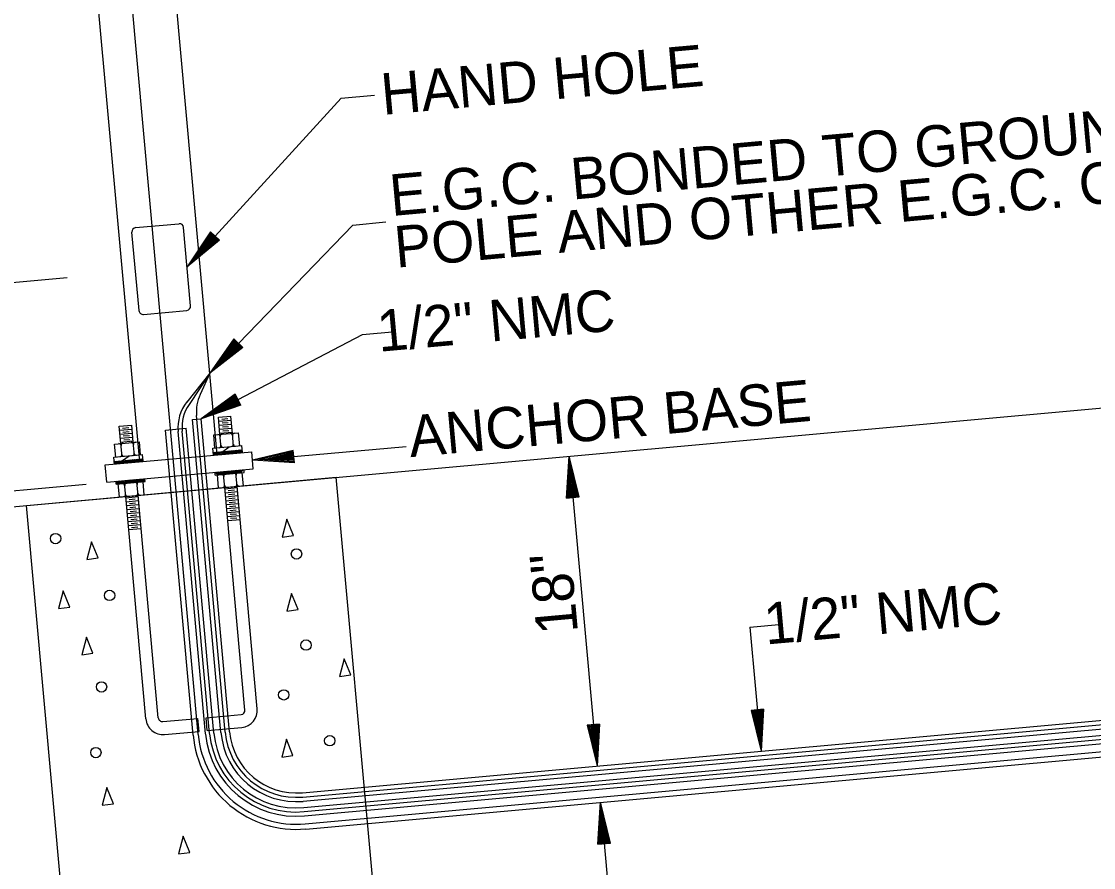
# Model space of a CAD drawing. Extents: x 1277218 to 1279252, y 196860 to 197529.
# Drawn here: x 1278336.3 to 1278454.9, y 197271.8 to 197365.4 of the extents above; entities that cross this region are included whole.
import ezdxf

# ---------------------------------------------------------------- set-up
doc = ezdxf.new("R2010")
doc.units = 0
doc.layers.add('R_Point Sym', color=7, linetype='Continuous')

msp = doc.modelspace()

# ---------------------------------------------------------------- linework, layer by layer
at = {"layer": 'R_Point Sym'}
for p, q in [((1278349.34, 197316.66), (1278341, 197408.77)), ((1278357.91, 197317.43), (1278349.57, 197409.55)), ((1278355.82, 197286.47), (1278346.71, 197386.98)), ((1278354.59, 197338.26), (1278371.65, 197356.9)), ((1278371.65, 197356.9), (1278375.32, 197357.23)), ((1278348.89, 197342.58), (1278353.69, 197343.01)), ((1278354.98, 197333.91), (1278354.19, 197342.6)), ((1278357.1, 197326.46), (1278372.92, 197342.87)), ((1278372.92, 197342.87), (1278376.59, 197343.21)), ((1278349.27, 197333.4), (1278348.48, 197342.08)), ((1278357.17, 197342.11), (1278354.59, 197338.26)), ((1278358.19, 197341.18), (1278354.59, 197338.26)), ((1278357.26, 197342.03), (1278355.1, 197338.82)), ((1278358.11, 197341.26), (1278355.1, 197338.82)), ((1278357.35, 197341.95), (1278355.64, 197339.41)), ((1278358.02, 197341.34), (1278355.64, 197339.41)), ((1278357.43, 197341.88), (1278356.15, 197339.97)), ((1278357.93, 197341.41), (1278356.15, 197339.97)), ((1278357.52, 197341.8), (1278356.68, 197340.54)), ((1278357.85, 197341.49), (1278356.68, 197340.54)), ((1278358.19, 197341.18), (1278357.17, 197342.11)), ((1278357.6, 197341.72), (1278357.19, 197341.11)), ((1278357.76, 197341.57), (1278357.19, 197341.11)), ((1278328.02, 197335.85), (1278341.33, 197337.06)), ((1278349.76, 197332.98), (1278354.56, 197333.42)), ((1278356.15, 197321.42), (1278374.02, 197330.76)), ((1278374.02, 197330.76), (1278377.68, 197331.09)), ((1278359.76, 197330.26), (1278357.1, 197326.46)), ((1278360.76, 197329.31), (1278357.1, 197326.46)), ((1278359.85, 197330.18), (1278357.62, 197327.02)), ((1278360.68, 197329.39), (1278357.62, 197327.02)), ((1278359.93, 197330.1), (1278358.17, 197327.59)), ((1278360.59, 197329.47), (1278358.17, 197327.59)), ((1278360.01, 197330.02), (1278358.7, 197328.14)), ((1278360.51, 197329.55), (1278358.7, 197328.14)), ((1278360.1, 197329.94), (1278359.23, 197328.7)), ((1278360.42, 197329.63), (1278359.23, 197328.7)), ((1278360.76, 197329.31), (1278359.76, 197330.26)), ((1278360.18, 197329.86), (1278359.76, 197329.26)), ((1278360.34, 197329.71), (1278359.76, 197329.26)), ((1278276.09, 197306.34), (1278517.66, 197328.23)), ((1278357.1, 197326.46), (1278354.57, 197323.28)), ((1278357.1, 197326.46), (1278354.8, 197323.02)), ((1278357.1, 197326.46), (1278356.03, 197324.11)), ((1278359.9, 197324.16), (1278356.15, 197321.42)), ((1278359.95, 197324.06), (1278356.83, 197321.78)), ((1278360.01, 197323.95), (1278357.53, 197322.14)), ((1278360.43, 197323.14), (1278357.53, 197322.14)), ((1278360.06, 197323.85), (1278358.21, 197322.5)), ((1278360.38, 197323.24), (1278358.21, 197322.5)), ((1278360.11, 197323.75), (1278358.9, 197322.86)), ((1278360.32, 197323.35), (1278358.9, 197322.86)), ((1278360.17, 197323.64), (1278359.58, 197323.21)), ((1278360.27, 197323.45), (1278359.58, 197323.21)), ((1278360.54, 197322.94), (1278359.9, 197324.16)), ((1278360.54, 197322.94), (1278356.15, 197321.42)), ((1278360.48, 197323.04), (1278356.83, 197321.78)), ((1278355.2, 197321.33), (1278356.15, 197321.42)), ((1278358.34, 197286.69), (1278355.2, 197321.33)), ((1278358.81, 197286.74), (1278355.64, 197321.8)), ((1278359.29, 197286.78), (1278356.15, 197321.42)), ((1278358.06, 197321.59), (1278359.43, 197321.72)), ((1278358.23, 197319.69), (1278358.06, 197321.59)), ((1278358.1, 197321.15), (1278359.47, 197321.28)), ((1278358.13, 197320.71), (1278359.51, 197320.84)), ((1278358.42, 197321.4), (1278359.1, 197321.46)), ((1278358.46, 197320.96), (1278359.14, 197321.02)), ((1278359.6, 197319.81), (1278359.43, 197321.72)), ((1278347.08, 197320.6), (1278348.46, 197320.72)), ((1278347.26, 197318.69), (1278347.08, 197320.6)), ((1278347.12, 197320.16), (1278348.5, 197320.28)), ((1278347.16, 197319.72), (1278348.54, 197319.84)), ((1278347.45, 197320.4), (1278348.13, 197320.46)), ((1278347.49, 197319.96), (1278348.17, 197320.02)), ((1278347.53, 197319.52), (1278348.21, 197319.58)), ((1278348.63, 197318.82), (1278348.46, 197320.72)), ((1278352.19, 197320.18), (1278354.48, 197320.38)), ((1278355.25, 197286.41), (1278352.19, 197320.18)), ((1278356.62, 197286.54), (1278353.59, 197320.01)), ((1278357.08, 197286.58), (1278354.05, 197320.06)), ((1278357.54, 197286.62), (1278354.48, 197320.38)), ((1278357.54, 197319.63), (1278360.28, 197319.88)), ((1278357.67, 197318.18), (1278357.54, 197319.63)), ((1278358.17, 197320.27), (1278359.55, 197320.4)), ((1278358.21, 197319.84), (1278359.59, 197319.96)), ((1278358.36, 197318.24), (1278358.23, 197319.69)), ((1278358.5, 197320.52), (1278359.18, 197320.58)), ((1278358.54, 197320.08), (1278359.22, 197320.14)), ((1278359.73, 197318.37), (1278359.6, 197319.81)), ((1278360.42, 197318.43), (1278360.28, 197319.88)), ((1278346.57, 197318.63), (1278349.31, 197318.88)), ((1278346.7, 197317.19), (1278346.57, 197318.63)), ((1278347.2, 197319.28), (1278348.58, 197319.4)), ((1278347.24, 197318.84), (1278348.62, 197318.97)), ((1278347.39, 197317.25), (1278347.26, 197318.69)), ((1278347.57, 197319.08), (1278348.25, 197319.15)), ((1278348.76, 197317.37), (1278348.63, 197318.82)), ((1278349.44, 197317.44), (1278349.31, 197318.88)), ((1278357.44, 197318.16), (1278360.64, 197318.45)), ((1278360.71, 197317.69), (1278360.64, 197318.45)), ((1278345.51, 197316.31), (1278361.74, 197317.78)), ((1278346.47, 197317.17), (1278349.67, 197317.46)), ((1278347.43, 197316.79), (1278348.19, 197317.31)), ((1278349.74, 197316.69), (1278349.67, 197317.46)), ((1278357.51, 197317.4), (1278357.44, 197318.16)), ((1278357.49, 197317.7), (1278360.69, 197317.99)), ((1278357.55, 197317.4), (1278357.82, 197317.73)), ((1278357.55, 197317.59), (1278357.66, 197317.72)), ((1278357.71, 197317.42), (1278357.9, 197317.64)), ((1278357.87, 197317.43), (1278357.91, 197317.48)), ((1278357.89, 197317.69), (1278357.94, 197317.74)), ((1278357.91, 197317.53), (1278358.1, 197317.76)), ((1278357.98, 197317.44), (1278358.26, 197317.77)), ((1278358.14, 197317.46), (1278358.4, 197317.77)), ((1278358.31, 197317.47), (1278358.42, 197317.6)), ((1278358.41, 197317.72), (1278358.46, 197317.79)), ((1278358.42, 197317.56), (1278358.63, 197317.81)), ((1278358.51, 197317.49), (1278358.79, 197317.82)), ((1278358.54, 197317.8), (1278359.25, 197318.32)), ((1278358.67, 197317.5), (1278358.95, 197317.84)), ((1278358.83, 197317.52), (1278359.11, 197317.85)), ((1278358.99, 197317.53), (1278359.27, 197317.86)), ((1278359.16, 197317.55), (1278359.43, 197317.88)), ((1278359.32, 197317.56), (1278359.59, 197317.89)), ((1278359.48, 197317.58), (1278359.76, 197317.91)), ((1278359.64, 197317.59), (1278359.78, 197317.76)), ((1278359.77, 197317.9), (1278359.78, 197317.91)), ((1278359.79, 197317.74), (1278359.94, 197317.93)), ((1278359.83, 197317.61), (1278360.11, 197317.94)), ((1278359.99, 197317.62), (1278360.27, 197317.96)), ((1278360.15, 197317.64), (1278360.43, 197317.97)), ((1278360.31, 197317.65), (1278360.59, 197317.98)), ((1278360.48, 197317.67), (1278360.64, 197317.87)), ((1278360.64, 197317.68), (1278360.69, 197317.75)), ((1278361.91, 197315.88), (1278361.74, 197317.78)), ((1278361.83, 197316.83), (1278378.84, 197318.37)), ((1278366.34, 197317.93), (1278361.83, 197316.83)), ((1278366.35, 197317.81), (1278362.59, 197316.9)), ((1278366.36, 197317.7), (1278363.38, 197316.97)), ((1278366.37, 197317.58), (1278364.14, 197317.04)), ((1278366.38, 197317.47), (1278364.91, 197317.11)), ((1278366.39, 197317.35), (1278365.68, 197317.18)), ((1278366.46, 197316.56), (1278366.34, 197317.93)), ((1278396.6, 197312.65), (1278396.87, 197317.28)), ((1278396.87, 197317.28), (1278399.98, 197283)), ((1278397.97, 197312.77), (1278396.87, 197317.28)), ((1278345.69, 197314.41), (1278345.51, 197316.31)), ((1278346.54, 197316.4), (1278346.47, 197317.17)), ((1278346.52, 197316.71), (1278349.72, 197317)), ((1278346.53, 197316.55), (1278346.67, 197316.72)), ((1278346.56, 197316.41), (1278346.84, 197316.74)), ((1278346.72, 197316.42), (1278347, 197316.75)), ((1278346.88, 197316.43), (1278347.16, 197316.77)), ((1278347.04, 197316.45), (1278347.32, 197316.78)), ((1278347.21, 197316.46), (1278347.43, 197316.74)), ((1278347.37, 197316.48), (1278347.45, 197316.58)), ((1278347.44, 197316.72), (1278347.5, 197316.8)), ((1278347.45, 197316.56), (1278347.66, 197316.81)), ((1278347.55, 197316.5), (1278347.83, 197316.83)), ((1278347.71, 197316.51), (1278347.99, 197316.84)), ((1278347.87, 197316.52), (1278348.15, 197316.86)), ((1278348.03, 197316.54), (1278348.31, 197316.87)), ((1278348.2, 197316.55), (1278348.47, 197316.89)), ((1278348.36, 197316.57), (1278348.63, 197316.9)), ((1278348.52, 197316.58), (1278348.8, 197316.92)), ((1278348.68, 197316.6), (1278348.81, 197316.76)), ((1278348.8, 197316.89), (1278348.83, 197316.92)), ((1278348.82, 197316.72), (1278348.99, 197316.93)), ((1278348.88, 197316.62), (1278349.15, 197316.95)), ((1278349.04, 197316.63), (1278349.32, 197316.96)), ((1278349.2, 197316.64), (1278349.33, 197316.8)), ((1278349.33, 197316.83), (1278349.44, 197316.97)), ((1278349.34, 197316.67), (1278349.6, 197316.99)), ((1278349.49, 197316.67), (1278349.72, 197316.95)), ((1278349.65, 197316.69), (1278349.73, 197316.79)), ((1278366.46, 197316.56), (1278361.83, 197316.83)), ((1278366.45, 197316.67), (1278362.59, 197316.9)), ((1278366.44, 197316.79), (1278363.38, 197316.97)), ((1278366.43, 197316.9), (1278364.14, 197317.04)), ((1278366.42, 197317.02), (1278364.91, 197317.11)), ((1278366.41, 197317.14), (1278365.68, 197317.18)), ((1278396.72, 197312.66), (1278396.94, 197316.52)), ((1278397.86, 197312.76), (1278396.94, 197316.52)), ((1278336.82, 197311.84), (1278371.1, 197314.95)), ((1278345.69, 197314.41), (1278361.91, 197315.88)), ((1278357.71, 197315.19), (1278357.69, 197315.49)), ((1278357.69, 197315.49), (1278357.7, 197315.49)), ((1278357.71, 197315.19), (1278360.91, 197315.48)), ((1278357.77, 197315.4), (1278357.86, 197315.51)), ((1278357.85, 197315.31), (1278358.02, 197315.52)), ((1278357.93, 197315.23), (1278358.19, 197315.54)), ((1278358.07, 197313.77), (1278357.94, 197315.21)), ((1278358.07, 197315.22), (1278358.35, 197315.55)), ((1278358.23, 197315.24), (1278358.51, 197315.57)), ((1278358.39, 197315.25), (1278358.61, 197315.51)), ((1278358.56, 197315.27), (1278358.62, 197315.34)), ((1278358.61, 197315.49), (1278358.68, 197315.58)), ((1278358.62, 197315.33), (1278358.84, 197315.6)), ((1278358.76, 197313.83), (1278358.63, 197315.27)), ((1278358.73, 197315.28), (1278359.01, 197315.61)), ((1278358.89, 197315.3), (1278359.17, 197315.63)), ((1278359.05, 197315.31), (1278359.33, 197315.64)), ((1278359.21, 197315.32), (1278359.49, 197315.66)), ((1278359.37, 197315.34), (1278359.65, 197315.67)), ((1278359.54, 197315.35), (1278359.81, 197315.69)), ((1278359.7, 197315.37), (1278359.97, 197315.7)), ((1278359.86, 197315.38), (1278359.99, 197315.54)), ((1278359.97, 197315.7), (1278359.97, 197315.7)), ((1278359.99, 197315.54), (1278360.14, 197315.72)), ((1278360.13, 197313.95), (1278360, 197315.4)), ((1278360.02, 197315.4), (1278360.3, 197315.73)), ((1278360.18, 197315.41), (1278360.46, 197315.74)), ((1278360.34, 197315.43), (1278360.62, 197315.76)), ((1278360.51, 197315.44), (1278360.78, 197315.77)), ((1278360.67, 197315.46), (1278360.73, 197315.53)), ((1278360.82, 197314.01), (1278360.69, 197315.46)), ((1278360.91, 197315.48), (1278360.89, 197315.78)), ((1278377.31, 197246.38), (1278371.1, 197314.95)), ((1278396.83, 197312.67), (1278397.01, 197315.73)), ((1278396.95, 197312.68), (1278397.08, 197314.97)), ((1278397.74, 197312.75), (1278397.01, 197315.73)), ((1278397.63, 197312.74), (1278397.08, 197314.97)), ((1278330.09, 197312.99), (1278343.4, 197314.2)), ((1278346.74, 197314.19), (1278346.72, 197314.5)), ((1278346.73, 197314.35), (1278346.87, 197314.51)), ((1278346.74, 197314.19), (1278349.94, 197314.48)), ((1278346.75, 197314.2), (1278347.03, 197314.53)), ((1278346.91, 197314.21), (1278347.19, 197314.54)), ((1278347.1, 197312.77), (1278346.97, 197314.22)), ((1278347.08, 197314.22), (1278347.35, 197314.56)), ((1278347.24, 197314.24), (1278347.51, 197314.57)), ((1278347.4, 197314.25), (1278347.63, 197314.54)), ((1278347.56, 197314.27), (1278347.65, 197314.37)), ((1278347.64, 197314.51), (1278347.7, 197314.59)), ((1278347.65, 197314.35), (1278347.87, 197314.6)), ((1278347.79, 197312.83), (1278347.66, 197314.28)), ((1278347.75, 197314.29), (1278348.03, 197314.62)), ((1278347.91, 197314.3), (1278348.19, 197314.63)), ((1278348.07, 197314.32), (1278348.35, 197314.65)), ((1278348.23, 197314.33), (1278348.51, 197314.66)), ((1278348.4, 197314.34), (1278348.67, 197314.68)), ((1278348.56, 197314.36), (1278348.84, 197314.69)), ((1278348.72, 197314.37), (1278349, 197314.71)), ((1278348.88, 197314.39), (1278349.02, 197314.55)), ((1278349.01, 197314.56), (1278349.14, 197314.72)), ((1278349.03, 197314.4), (1278349.31, 197314.73)), ((1278349.16, 197312.96), (1278349.03, 197314.4)), ((1278349.19, 197314.42), (1278349.47, 197314.75)), ((1278349.35, 197314.43), (1278349.63, 197314.76)), ((1278349.51, 197314.45), (1278349.79, 197314.78)), ((1278349.67, 197314.46), (1278349.92, 197314.75)), ((1278349.85, 197313.02), (1278349.71, 197314.46)), ((1278349.84, 197314.47), (1278349.93, 197314.59)), ((1278349.94, 197314.48), (1278349.92, 197314.79)), ((1278358.07, 197313.77), (1278360.82, 197314.01)), ((1278360.99, 197289.19), (1278358.76, 197313.83)), ((1278358.77, 197313.68), (1278360.14, 197313.81)), ((1278362.36, 197289.34), (1278360.13, 197313.95)), ((1278397.07, 197312.69), (1278397.15, 197314.2)), ((1278397.51, 197312.73), (1278397.15, 197314.2)), ((1278347.1, 197312.77), (1278349.85, 197313.02)), ((1278350.02, 197288.22), (1278347.79, 197312.83)), ((1278347.8, 197312.69), (1278349.17, 197312.81)), ((1278348.16, 197312.49), (1278348.85, 197312.55)), ((1278351.39, 197288.33), (1278349.16, 197312.96)), ((1278358.81, 197313.24), (1278360.18, 197313.37)), ((1278358.85, 197312.8), (1278360.22, 197312.93)), ((1278358.89, 197312.36), (1278360.26, 197312.49)), ((1278359.14, 197313.48), (1278359.82, 197313.55)), ((1278359.18, 197313.04), (1278359.86, 197313.11)), ((1278359.22, 197312.61), (1278359.9, 197312.67)), ((1278396.6, 197312.65), (1278397.97, 197312.77)), ((1278397.18, 197312.7), (1278397.22, 197313.43)), ((1278397.4, 197312.72), (1278397.22, 197313.43)), ((1278343.03, 197243.27), (1278336.82, 197311.84)), ((1278347.84, 197312.25), (1278349.21, 197312.37)), ((1278347.88, 197311.81), (1278349.25, 197311.93)), ((1278347.92, 197311.37), (1278349.29, 197311.49)), ((1278348.2, 197312.05), (1278348.89, 197312.11)), ((1278348.24, 197311.61), (1278348.93, 197311.67)), ((1278358.93, 197311.92), (1278360.3, 197312.05)), ((1278358.97, 197311.48), (1278360.34, 197311.61)), ((1278359.26, 197312.17), (1278359.94, 197312.23)), ((1278359.3, 197311.73), (1278359.98, 197311.79)), ((1278359.33, 197311.29), (1278360.02, 197311.35)), ((1278347.96, 197310.93), (1278349.33, 197311.05)), ((1278348, 197310.49), (1278349.37, 197310.61)), ((1278348.04, 197310.05), (1278349.41, 197310.17)), ((1278348.28, 197311.17), (1278348.97, 197311.23)), ((1278348.32, 197310.73), (1278349.01, 197310.79)), ((1278348.36, 197310.29), (1278349.05, 197310.35)), ((1278359.01, 197311.04), (1278360.38, 197311.17)), ((1278359.05, 197310.6), (1278360.42, 197310.73)), ((1278359.09, 197310.17), (1278360.46, 197310.29)), ((1278359.37, 197310.85), (1278360.06, 197310.91)), ((1278359.41, 197310.41), (1278360.1, 197310.47)), ((1278348.08, 197309.61), (1278349.45, 197309.73)), ((1278348.12, 197309.17), (1278349.49, 197309.3)), ((1278348.4, 197309.85), (1278349.09, 197309.91)), ((1278348.44, 197309.41), (1278349.13, 197309.48)), ((1278416.88, 197298.36), (1278420.5, 197298.69)), ((1278416.88, 197298.36), (1278418.12, 197284.64)), ((1278367.35, 197280.04), (1278480.42, 197290.29)), ((1278367.39, 197279.56), (1278479.34, 197289.71)), ((1278367.44, 197279.09), (1278480.51, 197289.33)), ((1278367.54, 197277.95), (1278486.95, 197288.77)), ((1278418.39, 197289.27), (1278417.02, 197289.15)), ((1278417.02, 197289.15), (1278418.12, 197284.64)), ((1278417.13, 197289.16), (1278418.05, 197285.4)), ((1278417.25, 197289.17), (1278417.98, 197286.19)), ((1278417.36, 197289.18), (1278417.91, 197286.95)), ((1278417.48, 197289.19), (1278417.84, 197287.73)), ((1278417.6, 197289.2), (1278417.77, 197288.49)), ((1278417.81, 197289.22), (1278417.77, 197288.49)), ((1278417.93, 197289.23), (1278417.84, 197287.73)), ((1278418.05, 197289.24), (1278417.91, 197286.95)), ((1278418.16, 197289.25), (1278417.98, 197286.19)), ((1278418.28, 197289.26), (1278418.05, 197285.4)), ((1278418.39, 197289.27), (1278418.12, 197284.64)), ((1278351.89, 197287.91), (1278355.78, 197288.26)), ((1278355.91, 197286.83), (1278355.78, 197288.26)), ((1278356.69, 197288.34), (1278360.58, 197288.7)), ((1278356.82, 197286.92), (1278356.69, 197288.34)), ((1278367.5, 197278.4), (1278480.57, 197288.65)), ((1278367.58, 197277.49), (1278483.67, 197288.01)), ((1278400.25, 197287.63), (1278398.88, 197287.51)), ((1278399.34, 197287.55), (1278399.7, 197286.08)), ((1278399.46, 197287.56), (1278399.63, 197286.85)), ((1278399.67, 197287.58), (1278399.63, 197286.85)), ((1278399.79, 197287.59), (1278399.7, 197286.08)), ((1278399.91, 197287.6), (1278399.77, 197285.31)), ((1278400.02, 197287.61), (1278399.84, 197284.55)), ((1278400.14, 197287.62), (1278399.91, 197283.76)), ((1278400.25, 197287.63), (1278399.98, 197283)), ((1278352.1, 197286.49), (1278355.91, 197286.83)), ((1278356.82, 197286.92), (1278360.63, 197287.26)), ((1278367.66, 197276.59), (1278480.73, 197286.84)), ((1278398.88, 197287.51), (1278399.98, 197283)), ((1278398.99, 197287.52), (1278399.91, 197283.76)), ((1278399.11, 197287.53), (1278399.84, 197284.55)), ((1278399.23, 197287.54), (1278399.77, 197285.31)), ((1278367.72, 197276.02), (1278480.78, 197286.27)), ((1278400.07, 197274.35), (1278400.34, 197278.98)), ((1278400.19, 197274.36), (1278400.41, 197278.22)), ((1278400.34, 197278.98), (1278401.9, 197261.8)), ((1278401.44, 197274.47), (1278400.34, 197278.98)), ((1278401.33, 197274.46), (1278400.41, 197278.22)), ((1278400.3, 197274.37), (1278400.48, 197277.43)), ((1278401.21, 197274.45), (1278400.48, 197277.43)), ((1278400.42, 197274.38), (1278400.55, 197276.67)), ((1278400.54, 197274.39), (1278400.62, 197275.89)), ((1278401.1, 197274.44), (1278400.55, 197276.67)), ((1278400.98, 197274.43), (1278400.62, 197275.89)), ((1278400.65, 197274.4), (1278400.69, 197275.13)), ((1278400.87, 197274.42), (1278400.69, 197275.13)), ((1278400.07, 197274.35), (1278401.44, 197274.47))]:
    msp.add_line(p, q, dxfattribs=at)
for points in [[(1278365.63, 197310.3), (1278365.11, 197308.34), (1278366.36, 197308.5), (1278365.63, 197310.3)], [(1278343.99, 197307.82), (1278343.48, 197305.86), (1278344.73, 197306.02), (1278343.99, 197307.82)], [(1278340.88, 197302.38), (1278340.36, 197300.42), (1278341.62, 197300.59), (1278340.88, 197302.38)], [(1278366.14, 197302.1), (1278365.62, 197300.14), (1278366.87, 197300.3), (1278366.14, 197302.1)], [(1278343.44, 197297.27), (1278342.92, 197295.31), (1278344.17, 197295.48), (1278343.44, 197297.27)], [(1278371.98, 197294.87), (1278371.46, 197292.91), (1278372.71, 197293.07), (1278371.98, 197294.87)], [(1278365.58, 197285.95), (1278365.06, 197283.99), (1278366.31, 197284.16), (1278365.58, 197285.95)], [(1278345.72, 197280.61), (1278345.2, 197278.65), (1278346.46, 197278.81), (1278345.72, 197280.61)], [(1278354.16, 197275.22), (1278353.64, 197273.26), (1278354.89, 197273.43), (1278354.16, 197275.22)]]:
    msp.add_lwpolyline(points, dxfattribs=at)
for centre in [(1278340.03, 197308.16), (1278366.7, 197306.46), (1278346.01, 197301.88), (1278367.75, 197296.38), (1278345.12, 197291.75), (1278365.28, 197290.87), (1278370.38, 197285.8), (1278344.49, 197284.48)]:
    msp.add_circle(centre, 0.574, dxfattribs=at)
for centre, radius, start, end in [((1278348.94, 197342.12), 0.459, 95.1779, 185.1779), ((1278353.74, 197342.56), 0.459, 5.1779, 95.1779), ((1278354.52, 197333.87), 0.459, 275.1779, 5.1779), ((1278349.72, 197333.44), 0.459, 185.1779, 275.1779), ((1278358.16, 197320.43), 4.59, 141.5009, 185.1779), ((1278360.21, 197322.21), 4.59, 155.5848, 185.1779), ((1278358.62, 197320.47), 4.59, 146.2959, 185.1779), ((1278358.02, 197319.44), 0.229, 5.1779, 95.1779), ((1278358.48, 197319.48), 0.229, 95.1779, 185.1779), ((1278359.39, 197319.56), 0.229, 5.1779, 95.1779), ((1278359.85, 197319.61), 0.229, 95.1779, 185.1779), ((1278347.05, 197318.45), 0.229, 5.1779, 95.1779), ((1278347.51, 197318.49), 0.229, 95.1779, 185.1779), ((1278348.42, 197318.57), 0.229, 5.1779, 95.1779), ((1278348.88, 197318.61), 0.229, 95.1779, 185.1779), ((1278358.11, 197318.45), 0.229, 275.1779, 5.1779), ((1278358.57, 197318.49), 0.229, 185.1779, 275.1779), ((1278359.48, 197318.58), 0.229, 275.1779, 5.1779), ((1278359.94, 197318.62), 0.229, 185.1779, 275.1779), ((1278347.14, 197317.46), 0.229, 275.1779, 5.1779), ((1278347.6, 197317.5), 0.229, 185.1779, 275.1779), ((1278348.51, 197317.58), 0.229, 275.1779, 5.1779), ((1278348.97, 197317.62), 0.229, 185.1779, 275.1779), ((1278358.42, 197315.02), 0.229, 5.1779, 95.1779), ((1278358.88, 197315.06), 0.229, 95.1779, 185.1779), ((1278359.79, 197315.15), 0.229, 5.1779, 95.1779), ((1278360.25, 197315.19), 0.229, 95.1779, 185.1779), ((1278347.45, 197314.03), 0.229, 5.1779, 95.1779), ((1278347.91, 197314.07), 0.229, 95.1779, 185.1779), ((1278348.82, 197314.15), 0.229, 5.1779, 95.1779), ((1278349.28, 197314.19), 0.229, 95.1779, 185.1779), ((1278358.51, 197314.04), 0.229, 275.1779, 5.1779), ((1278358.97, 197314.08), 0.229, 185.1779, 275.1779), ((1278359.88, 197314.16), 0.229, 275.1779, 5.1779), ((1278360.34, 197314.2), 0.229, 185.1779, 275.1779), ((1278347.54, 197313.04), 0.229, 275.1779, 5.1779), ((1278348, 197313.08), 0.229, 185.1779, 275.1779), ((1278348.91, 197313.17), 0.229, 275.1779, 5.1779), ((1278349.37, 197313.21), 0.229, 185.1779, 275.1779), ((1278360.53, 197289.15), 0.459, 275.1779, 5.1779), ((1278360.46, 197289.17), 1.91, 275.1779, 5.1779), ((1278351.92, 197288.39), 1.91, 185.1779, 275.1779), ((1278351.85, 197288.37), 0.459, 185.1779, 275.1779), ((1278366.68, 197287.45), 11.47, 185.1779, 275.1779), ((1278366.68, 197287.45), 10.9, 185.1779, 275.1779), ((1278366.63, 197287.49), 10.05, 185.4779, 275.4779), ((1278366.63, 197287.49), 9.59, 185.4779, 275.4779), ((1278366.63, 197287.49), 9.13, 185.4779, 275.4779), ((1278366.69, 197287.44), 8.39, 185.1126, 275.1126), ((1278366.69, 197287.44), 7.91, 185.1042, 275.1042), ((1278366.69, 197287.44), 7.43, 185.1042, 275.1042)]:
    msp.add_arc(centre, radius, start, end, dxfattribs=at)

# ---------------------------------------------------------------- texts
for s, height, rotation, p in [('HAND HOLE', 4.59, 5.1779, (1278376.26, 197355.05)), ('E.G.C. BONDED TO GROUND LUG ON ', 4.5899, 5.1779, (1278377.22, 197343.86)), ('POLE AND OTHER E.G.C. CONDUCTORS', 4.5899, 5.1779, (1278377.74, 197338.14)), (' 1/2" NMC ', 4.59, 5.1779, (1278374.13, 197328.68)), ('ANCHOR BASE', 4.5899, 5.1779, (1278379.31, 197317.17)), ('18"', 4.59, 95.1779, (1278397.86, 197297.79)), (' 1/2" NMC ', 4.59, 5.1779, (1278416.95, 197296.28))]:
    msp.add_text(s, height=height, rotation=rotation, dxfattribs=at).set_placement(p)

doc.saveas('drawing.dxf')
